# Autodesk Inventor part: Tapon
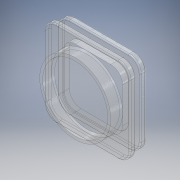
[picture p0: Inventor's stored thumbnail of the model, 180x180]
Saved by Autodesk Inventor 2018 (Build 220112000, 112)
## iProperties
Created: 2022-01
Part Number: Tapon
Material: Plástico, transparente
Document SubType Name: Modeling
Designer: Asus
Density: 1.188 g/cm^3
Appearance: Transparente - Claro
Author: Asus
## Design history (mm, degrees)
sketch "Boceto1"
  geometry: L1 (72.5, 72.5)-(-72.5, 72.5); L2 (-72.5, 72.5)-(-72.5, -72.5); L3 (-72.5, -72.5)-(72.5, -72.5); L4 (72.5, -72.5)-(72.5, 72.5); L5 (72.5, 72.5)-(-72.5, -72.5); L6 (-72.5, 72.5)-(72.5, -72.5); C1 r 60 at (0, 0); C2 r 55 at (0, 0); 1 further point
  constraints: 12 end point, 2 centre point, 2 coincident, 2 midpoint, 2 parallel, 1 horizontal, 1 perpendicular
  dimensions: "d0" = 120 diameter of C1; "d1" = 110 diameter of C2; "d2" = 145 distance of L3.end L2.end; "d3" = 145 distance of L2.end L1.end
extrude "Extrusión1" new body sketch "Boceto1" distance "d4" = 20; taper "d5" = 0 deg
extrude "Extrusión2" join sketch "Boceto1" distance "d6" = 10; taper "d7" = 0 deg
sketch "Boceto2"
  geometry: L1 (50, -50)-(-50, -50); L2 (-50, -50)-(-50, 50); L3 (-50, 50)-(50, 50); L4 (50, 50)-(50, -50); L5 (50, -50)-(-50, 50); L6 (-50, -50)-(50, 50); 1 further point
  constraints: 12 end point, 2 midpoint, 2 parallel, 1 horizontal, 1 perpendicular
  dimensions: "d8" = 100 distance of L2.end L3.end; "d9" = 100 distance of L1.end L2.end
extrude "Extrusión3" join sketch "Boceto2" distance "d10" = 10; taper "d11" = 0 deg
sketch "Boceto3"
  geometry: L1 (70, -70)-(-70, -70); L2 (-70, -70)-(-70, 70); L3 (-70, 70)-(70, 70); L4 (70, 70)-(70, -70); L5 (70, -70)-(-70, 70); L6 (-70, -70)-(70, 70); 1 further point
  constraints: 12 end point, 2 midpoint, 2 parallel, 1 horizontal, 1 perpendicular
  dimensions: "d12" = 140 distance of L2.end L3.end; "d13" = 140 distance of L1.end L2.end
extrude "Extrusión4" join sketch "Boceto3" distance "d14" = 10; taper "d15" = 0 deg
fillet "Empalme1" dims "d16" = 20
fillet "Empalme2" dims "d17" = 2
node "Sólido1"
